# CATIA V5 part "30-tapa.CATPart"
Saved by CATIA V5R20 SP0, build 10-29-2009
Part number: 30-tapa
Revision: ANY
Definition: UNKNOWN
Nomenclature: 30-tapa
Source: Unknown
Bounding box of the stored display mesh (mm): x -14.27 to 14.27, y -2.5 to 18.98, z -1 to 1.5
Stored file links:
  C:\Users\Utente\Desktop\IO LAVORO\3D X SITO CF\CUMSA\3D files CC\CCHS5328\30-tapa.CATPart
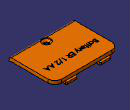
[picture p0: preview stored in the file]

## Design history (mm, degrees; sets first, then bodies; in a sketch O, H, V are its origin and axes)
Body1 "Redondeo9" (main body)
  Solid1: solid without history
